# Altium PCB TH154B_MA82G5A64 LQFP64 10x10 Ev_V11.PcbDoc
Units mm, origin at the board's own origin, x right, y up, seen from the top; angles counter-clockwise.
Board outline 72.4 x 66 mm, 2 copper layers (Top Layer, Bottom Layer); 55 components, 79 nets, 354 pads, 133 vias.
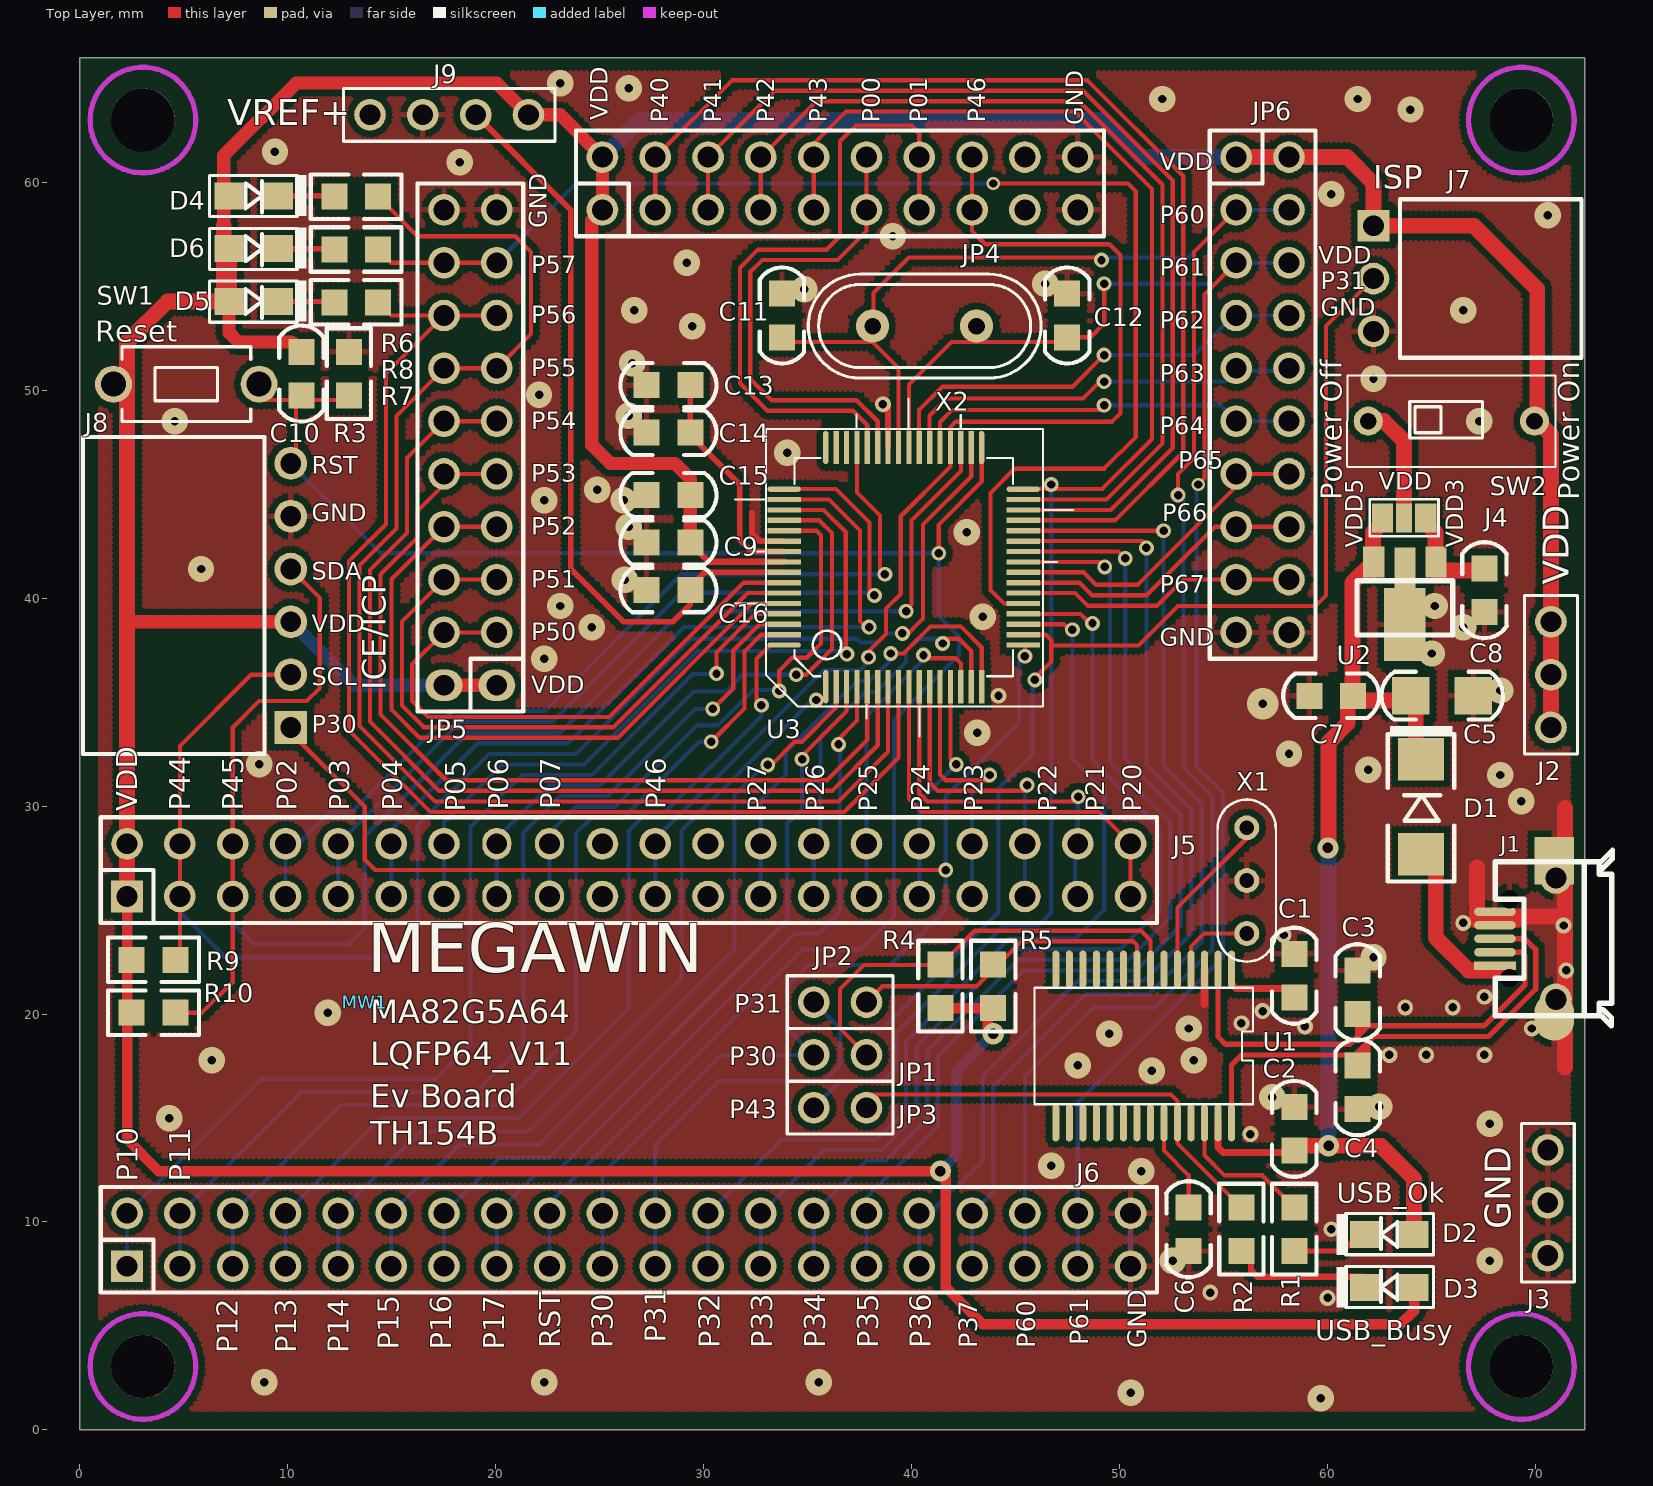
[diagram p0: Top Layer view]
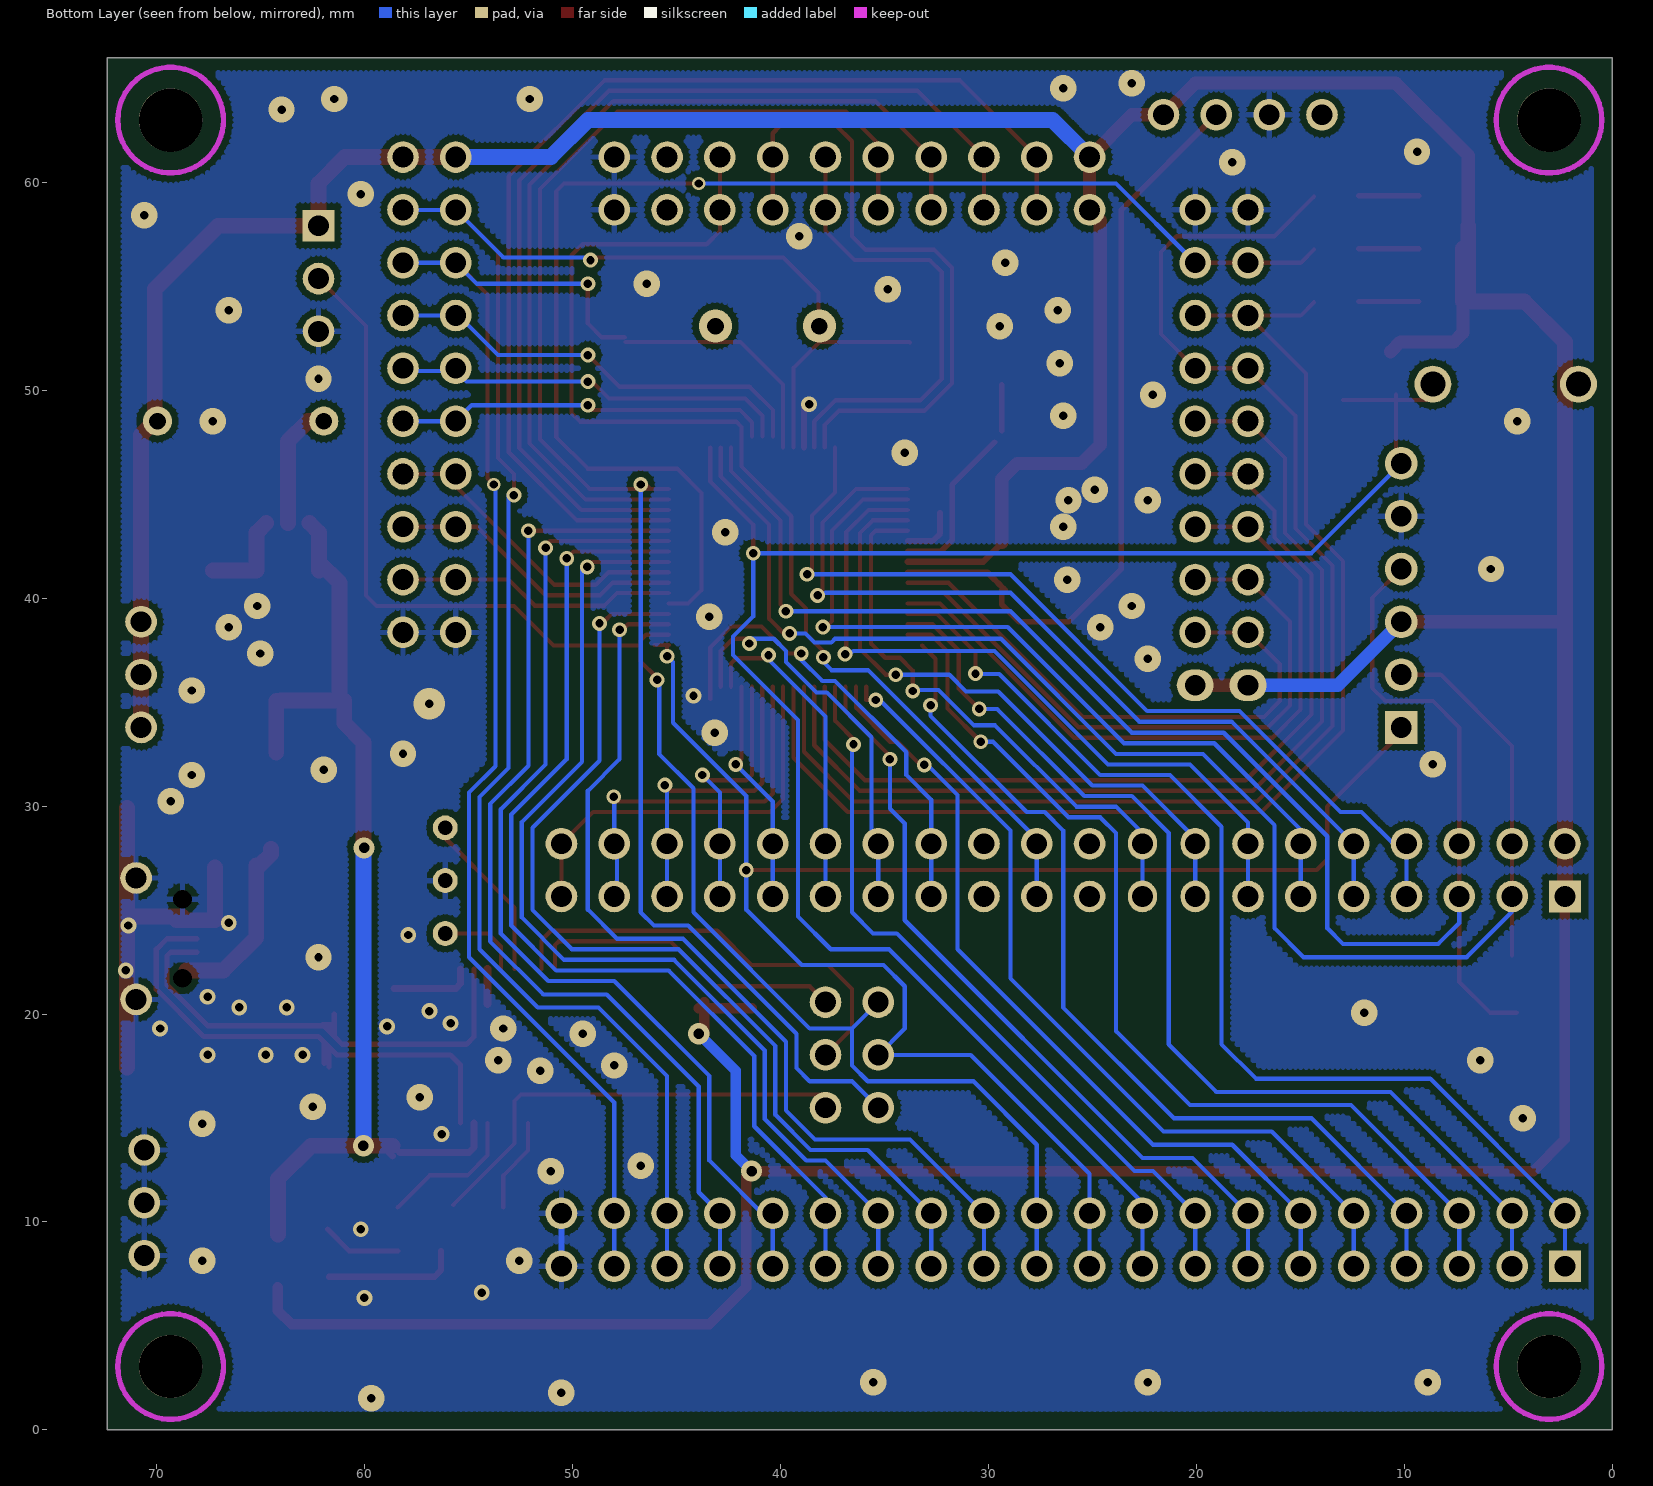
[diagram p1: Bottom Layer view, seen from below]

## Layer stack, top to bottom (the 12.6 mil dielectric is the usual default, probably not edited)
Top Layer: signal copper 0.0356
Dielectric: dielectric 0.32, FR-4, Dk 4.8
Bottom Layer: signal copper 0.0356

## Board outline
0,0 72.4,0 72.4,66 0,66

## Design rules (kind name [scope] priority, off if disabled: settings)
Clearance 12 [All] p1 off: gap=0.305
Clearance 10 [All] p2 off: gap=0.254
Clearance 6 [All] p3: gap=0.152
ComponentClearance [All] p1 off: gap=0.254 collisioncheckmode=3 verticalgap=0.254 showdistances=FALSE
HoleSize [All] p1: absolutevalues=TRUE maxlimit=12.7 minlimit=0.025 maxpercent=80.000 minpercent=20.000
MinimumSolderMaskSliver [All] p1 off: minsoldermaskwidth=0.254
PolygonConnect VIA [ISVIA] p1: connectstyle=Direct reliefconductorwidth=0.254 reliefentries=4 polygonreliefangle="90 Angle"
PolygonConnect [All] p2: connectstyle=Relief reliefconductorwidth=0.254 reliefentries=4 polygonreliefangle="90 Angle"
RoomDefinition "TH154B_MA82G5A64 LQFP64 10x10 Ev_V10" [InComponentClass('TH154B_MA82G5A64 LQFP64 10x10 Ev_V10')] p1: confinementstyle=ConfineIn formatcopy=TRUE lockcomponents=FALSE outline -6.858,-3.556 77.47,-3.556 77.47,69.85 -6.858,69.85
RoutingVias [All] p1: holewidth=0.406 width=0.635 viastyle="Through Hole" minholewidth=0.406 minwidth=0.61 maxholewidth=0.711 maxwidth=1.27
SilkToSilkClearance [All] p1 off: silktosilkclearance=0.254
SilkscreenOverComponentPads [All] p1 off: minsilkscreentomaskgap=0.254
SolderMaskExpansion [All] p1 off: expansion=0.102
Width [All] p1: maxlimit=5.08 minlimit=0.152 preferedwidth=0.254
23 further rules are at their usual default settings.

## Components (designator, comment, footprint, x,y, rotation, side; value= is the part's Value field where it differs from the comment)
C1 "4.7uF" 0805C 58.42,21.844 r90 top
C2 "0.1uF" 0805C 58.42,14.478 r270 top
C3 "15pF" 0805C 61.468,21.045 r90 top
C4 "15pF" 0805C 61.468,16.473 r270 top
C5 "4.7uF" 1206C 65.532,35.306 r0 top
C6 "0.1uF" 0805C 53.34,9.652 r90 top
C7 "0.1uF" 0805C 60.198,35.306 r180 top
C8 "4.7uF" 0805C 67.564,40.386 r270 top
C9 "0.1uF" 0805C 28.321,42.672 r0 top
C10 "1u" 0805C 10.668,50.8 r270 top
C11 "NC" 0805C 33.782,53.594 r90 top
C12 "NC" 0805C 47.498,53.594 r90 top
C13 "4.7uF" 0805C 28.321,50.245 r180 top
C14 "0.1uF" 0805C 28.321,47.959 r0 top
C15 "4.7uF" 0805C 28.321,44.958 r180 top
C16 "0.1uF" 0805C 28.321,40.386 r180 top
D1 "1N5817" D5817_SMD_1 64.516,29.972 r270 top
D2 "Yellow" 0805D 62.992,9.398 r180 top
D3 "Red" 0805D 62.992,6.858 r180 top
D4 "Green" 0805D 8.382,59.35 r0 top
D5 "Red" 0805D 8.382,54.27 r0 top
D6 "Green" 0805D 8.382,56.81 r0 top
J1 "Micro USB母座" JACK_USB_SMD290X220P065 68.072,23.622 r180 top
J2 "*" PS3P254 70.764,33.782 r90 top
J3 "*" PS3P254 70.612,13.462 r270 top
J4 "*" JUMP3_SMD 63.703,43.866 r0 top
J5 "*" PS20X2P254#1 2.286,25.654 r0 top
J6 "*" PS20X2P254#2 2.286,7.874 r0 top
J7 "*" PS3P254f_90 62.23,57.912 r270 top
J8 "*" PS6P254F_90 10.16,33.782 r90 top
J9 "CON4" PS4P254 21.59,63.246 r180 top
JP1 "JUMPER2" PS2P254 35.306,18.034 r0 top
JP2 "JUMPER2" PS2P254 35.306,20.574 r0 top
JP3 "JUMPER2" PS2P254 35.306,15.494 r0 top
JP4 "*" PS10X2P254#1 25.146,58.674 r0 top
JP5 "*" PS10X2P254#2 20.066,35.814 r90 top
JP6 "*" PS10X2P254#1 55.626,61.214 r270 top
MW1 "MW-A4" MEGAWIN_T 13.716,20.574 r0 top
R1 "1K" 0805R 58.42,9.652 r270 top
R2 "1K" 0805R 55.88,9.652 r270 top
R3 "47K" 0805R 12.954,50.8 r270 top
R4 "4.7K" 0805R 41.402,21.336 r90 top
R5 "4.7K" 0805R 43.942,21.336 r90 top
R6 "1K" 0805R 13.301,59.309 r180 top
R7 "1K" 0805R 13.301,54.229 r180 top
R8 "1K" 0805R 13.301,56.769 r180 top
R9 "4.7K" 0805R 3.556,22.606 r180 top
R10 "4.7K" 0805R 3.556,20.066 r180 top
SW1 "SW TACT-SPST" SW_T_2P 5.136,50.292 r0 top
SW2 "-" DIP2_SW 61.976,48.514 r0 top
U1 "MA101_TSSOP28" SSOP28_220P065 51.177,18.462 r180 top
U2 "AIC1734-33(SOT-89)" SOT89 63.74,41.732 r180 top
U3 "MA82G5A64 (10x10)" QFP64_10X10P050 35.886,35.744 r90 top locked (schematic designator U1)
X1 "6MHz" X3P 56.134,23.876 r90 top
X2 "NC" X49U 40.64,53.086 r180 top

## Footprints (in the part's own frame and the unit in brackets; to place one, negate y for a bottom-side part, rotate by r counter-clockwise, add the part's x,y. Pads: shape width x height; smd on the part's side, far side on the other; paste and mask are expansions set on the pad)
0805C [mm]
  rect 1.25x1.25 smd: 1(-1.05,0) 2(1.05,0)
  silkscreen extent -2.31,-1.07 2.31,1.07
0805D [mm]
  rect 1.4x1.3 smd: 1(-1.192,0) 2(1.192,0)
  silkscreen extent -2.12,-1 2.53,0.98
0805R [mm]
  rect 1.25x1.25 smd: 1(-1.05,0) 2(1.05,0)
  silkscreen extent -2.18,-1.07 2.18,1.07
1206C [mm]
  rect 1.8x1.8 smd: 1(-1.5,0) 2(1.5,0)
  silkscreen extent -2.92,-1.15 2.92,1.16
D5817_SMD_1 [mil]
  rect 80x86.61 smd: 1(90,0) 2(-90,0)
  silkscreen extent -153,-63 142,63
DIP2_SW [mm]
  round 1.4 hole 0.8: 1(0,0) 2(8,0)
  silkscreen extent -1.02,-2.2 9.02,2.2
JACK_USB_SMD290X220P065 [mm]
  rect 1.9x1.8 on Mech2: 0(-2.85,-1.15) 0(-2.85,1.15)
  round 0.8 hole 0.9 unplated: 1(-0.7,1.9) 5(-0.7,-1.9)
  rect 2x0.4 smd: 1(0,1.3)
  oval 2x0.4 smd: 2(0,0.65) 3(0,0) 4(0,-0.65) 5(0,-1.3)
  round 1.524 hole 1: 5(-2.931,2.921) 5(-2.931,-2.921)
  oval 1.9x2.3 smd: 5(-2.85,3.75)
  rect 1.9x2.3 smd: 5(-2.85,-3.75)
  silkscreen extent -5.65,-4.25 -0.01,4.2
JUMP3_SMD [mil]
  rect 40x55 smd: 1(-41,0) 3(41,0)
  rect 30x55 smd: 2(0,0)
  silkscreen extent -65,-35 65,35
MEGAWIN_T [mm]
PS2P254 [mil]
  round 60 hole 39.37: 1(0,0) 2(100,0)
  silkscreen extent -50,-50 150,50
PS3P254 [mil]
  round 60 hole 39.37: 1(0,0) 2(100,0) 3(200,0)
  silkscreen extent -50,-50 250,50
PS3P254f_90 [mil]
  rect 60x60 hole 39.37: 1(0,0)
  round 60 hole 39.37: 2(100,0) 3(200,0)
  silkscreen extent -50,50 250,394
PS4P254 [mil]
  round 60 hole 39.37: 1(0,0) 2(100,0) 3(200,0) 4(300,0)
  silkscreen extent -50,-50 350,50
PS6P254F_90 [mil]
  rect 62x62 hole 39.37: 1(0,0)
  round 62 hole 39.37: 2(100,0) 3(200,0) 4(300,0) 5(400,0) 6(500,0)
  silkscreen extent -50,50 550,394
PS10X2P254#1 [mil]
  round 60 hole 39.37: 1(0,0) 2(0,100) 3(100,0) 4(100,100) 5(200,0) 6(200,100) 7(300,0) 8(300,100) 9(400,0) 10(400,100) 11(500,0) 12(500,100) 13(600,0) 14(600,100) 15(700,0) 16(700,100) 17(800,0) 18(800,100) 19(900,0) 20(900,100)
  silkscreen extent -50,-50 950,150
PS10X2P254#2 [mil]
  oval 60x70 hole 39.37: 1(0,0) 2(0,100)
  round 60 hole 39.37: 3(100,0) 4(100,100) 5(200,0) 6(200,100) 7(300,0) 8(300,100) 9(400,0) 10(400,100) 11(500,0) 12(500,100) 13(600,0) 14(600,100) 15(700,0) 16(700,100) 17(800,0) 18(800,100) 19(900,0) 20(900,100)
  silkscreen extent -50,-50 950,150
PS20X2P254#1 [mil]
  rect 60x60 hole 39.37: 1(0,0)
  round 60 hole 39.37: 2(0,100) 3(100,0) 4(100,100) 5(200,0) 6(200,100) 7(300,0) 8(300,100) 9(400,0) 10(400,100) 11(500,0) 12(500,100) 13(600,0) 14(600,100) 19(900,0) 20(900,100) 21(1000,0) 22(1000,100) 23(1100,0) 24(1100,100) 25(1200,0) 26(1200,100) 27(1300,0) 28(1300,100) 29(1400,0) 30(1400,100) 31(1500,0) 32(1500,100) 33(1600,0) 34(1600,100) 35(1700,0) 36(1700,100) 37(1800,0) 38(1800,100) 39(1900,0) 40(1900,100)
  oval 55x60 hole 39.37: 15(700,0) 16(700,100) 17(800,0) 18(800,100)
  silkscreen extent -50,-50 1950,150
PS20X2P254#2 [mil]
  rect 60x60 hole 39.37: 1(0,0)
  round 60 hole 39.37: 2(0,100) 3(100,0) 4(100,100) 5(200,0) 6(200,100) 7(300,0) 8(300,100) 9(400,0) 10(400,100) 11(500,0) 12(500,100) 13(600,0) 14(600,100) 15(700,0) 16(700,100) 17(800,0) 18(800,100) 19(900,0) 20(900,100) 21(1000,0) 22(1000,100) 23(1100,0) 24(1100,100) 25(1200,0) 26(1200,100) 27(1300,0) 28(1300,100) 29(1400,0) 30(1400,100) 31(1500,0) 32(1500,100) 33(1600,0) 34(1600,100) 35(1700,0) 36(1700,100) 37(1800,0) 38(1800,100) 39(1900,0) 40(1900,100)
  silkscreen extent -50,-50 1950,150
QFP64_10X10P050 [mm]
  oval 1.6x0.254 smd: 1(0,0) 33(11.5,-7.5) 48(11.5,0)
  rect 1.6x0.254 smd: 2(0,-0.5) 3(0,-1) 4(0,-1.5) 5(0,-2) 6(0,-2.5) 7(0,-3) 8(0,-3.5) 9(0,-4) 10(0,-4.5) 11(0,-5) 12(0,-5.5) 13(0,-6) 14(0,-6.5) 15(0,-7) 16(0,-7.5) 34(11.5,-7) 35(11.5,-6.5) 36(11.5,-6) 37(11.5,-5.5) 38(11.5,-5) 39(11.5,-4.5) 40(11.5,-4) 41(11.5,-3.5) 42(11.5,-3) 43(11.5,-2.5) 44(11.5,-2) 45(11.5,-1.5) 46(11.5,-1) 47(11.5,-0.5)
  rect 0.254x1.6 smd: 17(2,-9.5) 18(2.5,-9.5) 19(3,-9.5) 20(3.5,-9.5) 21(4,-9.5) 22(4.5,-9.5) 23(5,-9.5) 24(5.5,-9.5) 25(6,-9.5) 26(6.5,-9.5) 27(7,-9.5) 28(7.5,-9.5) 29(8,-9.5) 30(8.5,-9.5) 31(9,-9.5) 50(9,2) 51(8.5,2) 52(8,2) 53(7.5,2) 54(7,2) 55(6.5,2) 56(6,2) 57(5.5,2) 58(5,2) 59(4.5,2) 60(4,2) 61(3.5,2) 62(3,2) 63(2.5,2)
  oval 0.254x1.6 smd: 32(9.5,-9.5) 49(9.5,2) 64(2,2)
  silkscreen extent -2.4,-11.9 13.86,4.36
SOT89 [mm]
  rect 1.016x1.5 smd: 1(-1.5,0) 3(1.5,0)
  rect 2x3.5 smd: 2(0,3)
  rect 1.016x2.6 smd: 2(0,0.6)
  silkscreen extent -2.3,0.9 2.3,3.5
SSOP28_220P065 [mm]
  oval 0.343x1.778 smd: 1(-4.225,-3.7) 2(-3.575,-3.7) 3(-2.925,-3.7) 4(-2.275,-3.7) 5(-1.625,-3.7) 6(-0.975,-3.7) 7(-0.325,-3.7) 8(0.325,-3.7) 9(0.975,-3.7) 10(1.625,-3.7) 11(2.275,-3.7) 12(2.925,-3.7) 13(3.575,-3.7) 14(4.225,-3.7) 15(4.225,3.7) 16(3.575,3.7) 17(2.925,3.7) 18(2.275,3.7) 19(1.625,3.7) 20(0.975,3.7) 21(0.325,3.7) 22(-0.325,3.7) 23(-0.975,3.7) 24(-1.625,3.7) 25(-2.275,3.7) 26(-2.925,3.7) 27(-3.575,3.7) 28(-4.225,3.7)
  silkscreen extent -5.25,-2.8 5.25,2.8
SW_T_2P [mm]
  round 1.778 hole 1.2: 1(-3.5,0) 2(3.5,0)
  silkscreen extent -3.1,-1.8 3.1,1.8
X3P [mm]
  round 1.2 hole 0.711: 1(0,0) 2(5.08,0) 3(2.54,0)
  silkscreen extent -1.36,-1.4 6.44,1.4
X49U [mm]
  round 1.6 hole 0.8: 1(-2.5,0) 2(2.5,0)
  silkscreen extent -5.6,-2.5 5.6,2.5

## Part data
C1 C5 C8 C13 C15: library part CAP
C2 C3 C4 C6 C7 C9 C14 C16: library part "CAP NP"
C10: library part C
C11 C12: library part "C NP"
D1: library part DIODE_ZD, "Schottky Diode"
D2 D3 D4 D5 D6: library part LED
J1: library part CON5, "Connector"
J2 J3 J4 J7: library part CON3
J5 J6: library part CON40A
J8: library part CON6
JP4 JP5 JP6: library part CON10X2
R1 R2 R4 R5 R6 R7 R8: library part R_Dup1
R3 R9 R10: library part R
SW2: library part SW-2
U2: library part AIC1734-33(SOT-89)_0
U3: library part MG82FG5A64_LQFP64
X1: library part CRYSTAL_RC
X2: library part CRYSTAL

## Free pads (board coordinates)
  round 3.048 hole 3.048 unplated: 0(3.048,3.048) 0(3.048,62.992) 0(69.342,3.048) 0(69.342,62.992)

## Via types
v1: diameter 1.27, hole 0.406, Top Layer to Bottom Layer, tented both sides, 65 vias
v2: diameter 0.711, hole 0.406, Top Layer to Bottom Layer, tented both sides, 41 vias
v3: diameter 0.762, hole 0.406, Top Layer to Bottom Layer, tented both sides, 20 vias
v4: diameter 1.016, hole 0.508, Top Layer to Bottom Layer, tented both sides, 4 vias
v5: diameter 0.635, hole 0.406, Top Layer to Bottom Layer, tented both sides, 2 vias
v6: diameter 1.524, hole 0.406, Top Layer to Bottom Layer, tented both sides, 1 vias

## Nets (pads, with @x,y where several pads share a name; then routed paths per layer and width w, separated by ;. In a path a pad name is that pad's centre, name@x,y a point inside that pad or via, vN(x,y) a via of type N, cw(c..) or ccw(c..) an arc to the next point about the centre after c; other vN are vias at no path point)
D+: C4.1 J1.3 U1.28 | length 24.9
  Top Layer w0.254: U1.28 55.402,17.556 55.88,18.034 61.341,18.034 62.23,18.923 67.76,18.923 70.028,21.191 70.028,23.112 69.518,23.622 J1.3 ; C4.1@61.722,17.45 61.722,18.39 ; C4.1@61.951,17.628 61.951,18.567
D-: C3.1 J1.2 U1.2 | length 24.3
  Top Layer w0.254: U1.2 54.752,18.908 55.118,18.542 61.087,18.542 61.468,18.923 ; C3.1 C3.1@61.468,19.486 ; 61.62,19.279 61.692,19.351 ; C3.1@61.722,19.431 C3.1@61.976,19.431 ; J1.2 69.353,22.972 69.52,22.805 69.52,21.401 67.55,19.431 C3.1@61.976,19.431 ; 61.468,18.923 C3.1@61.976,19.431 ; 61.468,18.923 C3.1@61.468,19.486 ; C3.1@61.468,19.486 62.031,19.486 C3.1@61.976,19.431
GND_POWER: C1.2 C2.1 C3.2 C4.2 C5.2 C6.1 C7.2 C8.2 C9.1 C11.2 C12.2 C13.2 C14.1 C15.2 C16.2 J1.4 J1.5 J3.1 J3.2 J3.3 J6.39 J6.40 J7.3 J8.5 J9.3 JP4.19 JP4.20 JP5.19 JP5.20 JP6.19 JP6.20 R3.1 U1.3 U2.2 U3.42 U3.54 X1.3 | length 28.3
  Top Layer w0.279: 32.334,44.094 32.334,43.104 32.694,42.744 U3.54 ; U3.42 v3@38.886,49.327
  Top Layer w0.381: 54.102,20.472 U1.3
  Top Layer w0.762: 67.205,24.512 69.07,24.512 ; 67.205,24.578 67.205,27.044 ; 68.797,24.69 71.263,24.69 ; 71.447,17.424 71.447,22.098 71.447,29.914
  Bottom Layer w0.279: J6.39 J6.40
  other v1: 59.69,1.524 50.546,1.778 8.89,2.286 22.352,2.286 35.56,2.286 52.578,8.128 67.818,8.128 51.054,12.446 46.736,12.7 67.818,14.732 4.318,14.986 62.509,15.545 57.353,16.002 51.562,17.272 48.006,17.526 6.35,17.78 53.594,17.78 49.53,19.05 53.34,19.304 11.938,20.066 62.23,22.733 69.342,30.226 68.326,31.496 61.976,31.75 8.636,32.004 58.166,32.512 43.18,33.528 68.326,35.56 22.352,37.084 65.024,37.338 24.638,38.608 66.548,38.608 43.434,39.116 23.114,39.624 65.172,39.624 26.214,40.894 5.842,41.402 42.672,43.18 26.416,43.434 22.352,44.704 26.162,44.704 24.892,45.212 34.036,46.99 4.572,48.514 67.31,48.514 26.416,48.768 22.098,49.784 62.23,50.546 26.581,51.306 29.464,53.086 26.67,53.848 66.548,53.848 34.849,54.864 46.441,55.118 29.21,56.134 39.116,57.404 70.612,58.42 60.198,59.436 18.288,60.96 9.398,61.468 64.008,63.5 52.07,64.008 61.468,64.008 26.416,64.516 23.114,64.77
  other v3: 60.02,6.35 54.381,6.604 60.198,9.652 56.312,14.224 62.992,18.034 64.77,18.034 67.564,18.034 69.85,19.304 58.928,19.406 55.88,19.558 56.896,20.142 63.754,20.32 66.04,20.32 67.564,20.828 71.501,22.098 57.912,23.8 71.374,24.257 66.548,24.384 44.196,35.306 38.633,49.327
  other v6: 56.902,34.928
MA101_RX: JP2.2 R5.2 U1.8 | length 15.6
  Top Layer w0.203: JP2.2 38.608,21.336 43.136,21.336 45.295,23.495 50.673,23.495 50.852,23.316 U1.8 U1.8@50.852,22.277
MA101_TX: JP1.2 R4.2 U1.7 | length 25.3
  Top Layer w0.203: JP1.2 36.576,19.304 36.576,21.209 37.719,22.352 41.402,22.352 43.053,24.003 48.768,24.003 ; 44.831,24.003 48.768,24.003 ; U1.7@51.502,22.165 U1.7 51.502,23.549 51.048,24.003 48.768,24.003
NetC1_1: C1.1 U1.1 | length 4.5
  Top Layer w0.33: U1.1@55.402,21.687 U1.1 55.402,21.458 55.626,21.234 C1.1@58.598,21.234
NetC6_2: C6.2 U1.23 | length 4.6
  Top Layer w0.203: U1.23 52.152,13.431 53.34,12.243 C6.2
NetC13_1: C13.1 C14.2 U3.55 | length 10.1
  Top Layer w0.279: C14.2@29.371,48.052 C13.1 ; C14.2@29.718,47.498 31.75,45.466 31.75,42.799 32.305,42.244 U3.55
NetD1_1: D1.1 J1.1 | length 8.5
  Top Layer w0.762: D1.1@64.516,27.94 D1.1 D1.1@65.024,27.178 ; D1.1@65.227,27.153 65.227,23.673 66.802,22.098 68.58,22.098
NetD2_2: D2.2 R1.2 | length 3.8
  Top Layer w0.254: R1.2 60.75,8.602 D2.2@61.8,9.652
NetD3_2: D3.2 R2.2 | length 6.4
  Top Layer w0.305: R2.2@56.337,8.602 56.337,7.671 56.642,7.366 D3.2@61.724,7.366
NetD4_2: D4.2 R6.2 | length 2.9
  Top Layer w0.254: D4.2@9.32,59.35 D4.2 R6.2@12.21,59.35
NetD5_2: D5.2 R7.2 | length 2.9
  Top Layer w0.254: D5.2@9.32,54.27 D5.2 R7.2@12.21,54.27
NetD6_2: D6.2 R8.2 | length 2.9
  Top Layer w0.254: D6.2@9.32,56.81 D6.2 R8.2@12.21,56.81
NetJ4_2: J4.2 SW2.1 | length 6.1
  Top Layer w0.762: SW2.1 62.738,48.514 63.703,47.549 J4.2 J4.2@63.703,43.612
NetU1_4: U1.4 X1.1 | length 4.5
  Top Layer w0.203: U1.4 53.452,23.241 54.087,23.876 X1.1 X1.1@56.642,23.876
NetU1_5: U1.5 X1.2 | length 8.4
  Top Layer w0.203: U1.5 52.802,25.116 X1.2@56.642,28.956
P00: JP4.11 JP4.12 U3.43 | length 23.3
  Top Layer w0.203: JP4.12 JP4.11 37.846,57.658 36.449,56.261 32.838,56.261 32.258,55.681 32.258,50.546 33.29,49.514 37.379,49.514 38.386,48.507 U3.43
P01: JP4.13 JP4.14 U3.44 | length 31.6
  Top Layer w0.203: U3.44 37.886,48.332 37.204,49.014 33.083,49.014 31.758,50.339 31.758,55.888 32.631,56.761 35.933,56.761 36.576,57.404 36.576,61.976 37.338,62.738 40.005,62.738 40.386,62.357 JP4.14 JP4.13
P02: J5.7 J5.8 U3.45 | length 43.3
  Top Layer w0.203: U3.45 37.386,45.08 38.498,43.967 v2@38.498,41.148
  Bottom Layer w0.203: J5.7 J5.8 10.541,28.194 12.065,29.718 13.081,29.718 17.932,34.569 22.377,34.569 28.956,41.148 v2(38.735,41.148)
P03: J5.9 J5.10 U3.49 | length 41.2
  Top Layer w0.203: U3.49 36.384,45.244 37.99,43.637 v2@37.99,40.132
  Bottom Layer w0.203: J5.9 J5.10 18.313,34.061 22.758,34.061 28.956,40.259 37.846,40.259
  other v2: 38.227,40.132
P04: J5.11 J5.12 U3.50 | length 39.3
  Top Layer w0.203: U3.50 36.045,44.744 37.533,43.256 37.533,38.895 v2@37.897,38.532
  Bottom Layer w0.203: J5.11 J5.12 14.986,28.854 19.152,33.02 23.495,33.02 29.083,38.608 37.821,38.608 v2@37.897,38.532
  other v2: 37.973,38.608
P05: J5.13 J5.14 U3.51 | length 35.8
  Top Layer w0.203: U3.51 35.783,44.244 36.847,43.18 36.847,37.397 v2@36.982,37.262
  Bottom Layer w0.203: J5.13 J5.14 17.526,29.21 20.32,32.004 24.257,32.004 29.718,37.465 36.516,37.465 v2@36.847,37.133
  other v2: 36.906,37.313
P06: J5.15 J5.16 U3.52 | length 30.8
  Top Layer w0.203: U3.52 35.572,43.744 36.187,43.129 36.187,37.559 34.95,36.322 v2(34.468,36.322)
  Bottom Layer w0.203: J5.15 J5.16 20.066,28.448 22.606,30.988 25.019,30.988 29.54,35.509 31.085,35.509 31.898,36.322 v2(34.468,36.322)
P07: J5.17 J5.18 U3.53 | length 27.5
  Top Layer w0.203: v2(33.655,35.535) 33.655,36.525 34.263,37.133 34.974,37.133 35.654,37.813 35.654,43.028 35.437,43.244 U3.53
  Bottom Layer w0.203: J5.17 J5.18 22.606,28.702 23.876,29.972 25.781,29.972 29.693,33.884 30.709,33.884 32.41,35.585 v2@33.655,35.585
P10: J6.1 J6.2 U3.61 | length 52.8
  Top Layer w0.203: v2(30.632,36.373) 30.632,37.389 32.488,39.244 U3.61
  Bottom Layer w0.203: J6.1 J6.2 8.763,16.891 17.145,16.891 18.796,18.542 18.796,29.007 21.285,31.496 24.638,31.496 29.489,36.347 v2@30.632,36.347
P11: J6.3 J6.4 U3.62 | length 51.6
  Top Layer w0.203: v2(30.455,34.671) 31.441,35.657 31.441,37.486 32.699,38.744 U3.62
  Bottom Layer w0.203: J6.3 J6.4 10.668,16.256 19.05,16.256 21.336,18.542 21.336,25.4 ; 21.336,24.13 21.336,25.4 ; v2(30.455,34.671) 29.591,34.671 25.4,30.48 23.114,30.48 21.336,28.702 21.336,25.4
P12: J6.5 J6.6 U3.63 | length 48
  Top Layer w0.203: v2(30.378,33.096) 31.979,34.696 31.979,37.44 32.783,38.244 U3.63
  Bottom Layer w0.203: J6.5 J6.6 12.573,15.621 20.32,15.621 23.876,19.177 23.876,23.622 ; 23.876,23.368 23.876,23.622 ; v2(30.378,33.096) 29.794,33.096 26.162,29.464 24.638,29.464 23.876,28.702 23.876,23.622
P13: J6.7 J6.8 U3.64 | length 44.6
  Top Layer w0.203: v2@32.563,34.849 32.563,37.084 U3.64@33.198,37.719
  Bottom Layer w0.203: J6.7 J6.8 14.478,14.986 21.082,14.986 26.416,20.32 26.416,24.003 ; 26.416,23.368 26.416,24.003 ; v2(32.791,34.849) 32.791,34.341 28.169,29.718 27.305,29.718 26.416,28.829 26.416,24.003
P14: J6.9 J6.10 U3.1 | length 41.6
  Top Layer w0.203: v2@35.501,35.103 35.886,35.103 U3.1 U3.1@35.886,35.306
  Bottom Layer w0.203: J6.9 J6.10 16.383,14.351 21.59,14.351 28.956,21.717 28.956,24.384 ; 28.956,24.13 28.956,24.384 ; v2@35.331,35.204 28.956,28.829 28.956,24.384
  other v2: 35.433,35.103
P15: J6.11 J6.12 U3.2 | length 39.4
  Top Layer w0.203: v2(33.096,31.979) 33.096,32.055 33.35,32.055 34.392,33.096 34.747,33.096 36.386,34.735 U3.2
  Bottom Layer w0.203: J6.11 J6.12 18.288,13.716 22.098,13.716 31.496,23.114 31.496,30.531 v2@33.02,32.055
P16: J6.13 J6.14 U3.3 | length 37.3
  Top Layer w0.203: v2@34.671,32.334 36.886,34.549 U3.3
  Bottom Layer w0.203: J6.13 J6.14 20.193,13.081 22.606,13.081 34.036,24.511 34.036,29.159 34.747,29.87 v2(34.747,32.258)
P17: J6.15 J6.16 U3.4 | length 36.2
  Top Layer w0.203: v2@36.373,33.096 37.386,34.109 U3.4
  Bottom Layer w0.203: J6.15 J6.16 22.098,12.446 22.987,12.446 34.417,23.876 35.56,23.876 36.576,24.892 v2@36.576,32.969
  other v2: 36.5,32.969
P20: J5.39 J5.40 U3.9 | length 19.5
  Top Layer w0.203: U3.9 39.886,30.345 40.513,29.718 49.022,29.718 J5.40 J5.39
P21: J5.37 J5.38 U3.10 | length 17.9
  Top Layer w0.203: U3.10 40.386,30.607 40.767,30.226 v2@48.031,30.226
  Bottom Layer w0.203: J5.38@47.879,28.194 47.879,25.781 J5.37 ; J5.38 v2@48.006,30.582
  other v2: 48.031,30.455
P22: J5.35 J5.36 U3.11 | length 14.9
  Top Layer w0.203: U3.11 40.886,31.123 41.275,30.734 v2@45.568,30.734
  Bottom Layer w0.203: J5.35 J5.36 45.466,30.912 v2(45.568,31.013)
P23: J5.33 J5.34 U3.12 | length 12.9
  Top Layer w0.203: U3.12 41.386,31.512 41.656,31.242 v2@43.764,31.242
  Bottom Layer w0.203: J5.33 J5.34 42.926,30.658 v2(43.764,31.496)
P24: J5.31 J5.32 U3.13 | length 10.9
  Top Layer w0.203: U3.13 41.886,32.282 v2(42.164,32.004)
  Bottom Layer w0.203: J5.31 J5.32 40.386,30.226 v2(42.164,32.004)
P25: J5.29 J5.30 U3.14 | length 15.6
  Top Layer w0.203: v2(40.589,37.262) 40.742,37.109 42.139,37.109 42.386,36.862 U3.14
  Bottom Layer w0.203: J5.29 J5.30 37.846,34.315 v2@40.589,37.059
P26: J5.27 J5.28 U3.15 | length 19
  Top Layer w0.203: v2@41.504,38.049 42.291,38.049 42.886,37.454 U3.15
  Bottom Layer w0.203: J5.27 J5.28 ; J5.28@35.636,28.524 35.636,29.718 ; 35.636,29.566 35.636,29.718 ; v2@41.504,38.049 40.335,38.049 39.751,37.465 39.751,36.932 38.278,35.458 37.783,35.458 35.636,33.312 35.636,29.718
  other v2: 41.504,37.821
P27: J5.25 J5.26 U3.16 | length 22.4
  Top Layer w0.203: v2(39.014,37.338) 39.624,37.338 40.919,38.633 42.393,38.633 43.386,37.64 U3.16 U3.16@43.386,35.15
  Bottom Layer w0.203: J5.25 J5.26 32.766,30.302 33.96,31.496 33.96,32.588 37.389,36.017 37.998,36.017 39.014,37.033 v2(39.014,37.338)
P30/RXD: J6.19 J6.20 J8.1 JP1.1 U3.17 | length 80.7
  Top Layer w0.203: J8.1@10.16,33.528 13.716,29.972 13.716,27.432 14.224,26.924 v2(41.656,26.924) ; U3.17 U3.17@45.466,37.744 ; v2(45.466,37.211) U3.17@45.466,37.744 ; U3.17@46.076,37.744 U3.17@45.466,37.744
  Bottom Layer w0.203: J6.19 J6.20 25.146,12.319 30.861,18.034 JP1.1 34.036,19.304 34.036,21.336 35.052,22.352 38.989,22.352 41.656,25.019 v2(41.656,26.924) 41.656,30.48 45.187,34.011 45.187,36.932 v2(45.466,37.211)
P31/TXD: J6.21 J6.22 J7.2 JP2.1 U3.18 | length 75.6
  Top Layer w0.203: U3.18 46.465,38.244 46.736,37.973 46.736,37.719 ; v2@45.974,36.195 46.736,36.957 46.736,37.719 ; J7.2 59.944,53.086 59.944,40.132 59.436,39.624 52.832,39.624 50.927,37.719 46.736,37.719
  Bottom Layer w0.203: J6.21 J6.22 27.686,13.716 30.734,16.764 35.814,16.764 36.576,17.526 36.576,19.304 ; JP2.1 36.576,19.304 ; v2@45.847,36.068 45.847,32.512 44.196,30.861 44.196,24.892 38.608,19.304 36.576,19.304
  other v2: 45.949,36.068
P32: J6.23 J6.24 U3.19 | length 46.1
  Top Layer w0.203: U3.19 47.337,38.744 v2@47.676,38.405
  Bottom Layer w0.203: J6.23 J6.24 33.782,13.97 38.354,13.97 39.751,15.367 39.751,18.669 44.704,23.622 47.879,23.622 49.276,25.019 49.276,30.734 47.752,32.258 v2(47.752,38.481)
P33: J6.25 J6.26 U3.20 | length 48
  Top Layer w0.203: U3.20 48.132,39.244 v2@48.463,38.913
  Bottom Layer w0.203: J6.25 J6.26 35.814,13.462 38.564,13.462 40.259,15.157 40.259,18.459 44.914,23.114 50.045,23.114 51.943,25.012 51.943,28.956 48.717,32.182 v2(48.717,38.786)
P34: J6.27 J6.28 U3.25 | length 49.8
  Top Layer w0.203: U3.25 49.061,41.744 v2(49.305,41.5)
  Bottom Layer w0.203: J6.27 J6.28 37.846,12.954 38.775,12.954 40.767,14.946 40.767,18.248 45.125,22.606 50.419,22.606 52.451,24.638 52.451,29.235 49.559,32.128 49.559,41.5 v2(49.305,41.5)
P35: J6.29 J6.30 U3.26 | length 49.6
  Top Layer w0.203: U3.26 49.958,42.244 v2(50.292,41.91)
  Bottom Layer w0.203: J6.29 J6.30 37.846,11.176 41.275,14.605 41.275,17.983 45.39,22.098 50.8,22.098 52.959,24.257 52.959,29.591 50.292,32.258 v2(50.292,41.91)
P36: J6.31 J6.32 U3.27 | length 48.4
  Top Layer w0.203: U3.27 51.109,42.744
  Bottom Layer w0.203: J6.31 40.386,9.906 43.434,12.954 43.434,17.018 48.006,21.59 51.181,21.59 53.467,23.876 53.467,29.845 51.308,32.004 v2(51.308,42.418)
P37: J6.33 J6.34 U3.28 | length 49.2
  Top Layer w0.203: U3.28 v2(52.133,43.244)
  Bottom Layer w0.203: J6.33 J6.34 43.942,11.43 43.942,16.51 48.368,20.936 51.416,20.936 53.975,23.495 53.975,30.099 52.133,31.941 v2(52.133,43.244)
P40: JP4.3 JP4.4 U3.29 | length 53.7
  Top Layer w0.203: JP4.3 JP4.4 31.376,64.904 48.47,64.904 53.078,60.295 53.078,47.02 49.802,43.744 U3.29
P41: JP4.5 JP4.6 U3.30 | length 49.3
  Top Layer w0.203: JP4.5 JP4.6 33.416,64.404 48.262,64.404 52.578,60.088 52.578,47.227 49.595,44.244 U3.30
P42: JP4.7 JP4.8 U3.31 | length 44.9
  Top Layer w0.203: JP4.7 JP4.8 35.456,63.904 48.055,63.904 52.078,59.881 52.078,47.434 49.388,44.744 U3.31
P43: JP3.1 JP4.9 JP4.10 U3.32 | length 78
  Top Layer w0.203: JP4.9 JP4.10 35.306,61.849 36.861,63.404 47.848,63.404 51.578,59.674 51.578,47.641 49.181,45.244 46.26,45.244 ; U3.32 46.26,45.244 ; v2@46.609,45.593 46.26,45.244
  Bottom Layer w0.203: JP3.1 36.576,16.764 38.608,16.764 39.243,17.399 39.243,19.05 44.45,24.257 46.101,24.257 46.736,24.892 v2@46.736,45.244
  other v2: 46.736,45.466
P44: J5.3 J5.4 J8.2 R9.1 U3.34 | length 73.5
  Top Layer w0.203: R9.1@4.826,22.826 J5.3 J5.4 4.826,32.893 8.255,36.322 J8.2 ; v2@39.713,38.163 40.564,39.014 40.564,43.536 42.886,45.858 U3.34
  Bottom Layer w0.203: J5.3 4.826,24.917 7.01,22.733 14.859,22.733 16.256,24.13 16.256,29.083 19.685,32.512 23.876,32.512 29.413,38.049 37.389,38.049 37.567,37.871 38.379,37.871 38.811,38.303 v2(39.573,38.303) ; J5.4 J5.4@4.826,28.575
P45: J5.5 J5.6 J8.4 R10.1 U3.35 | length 80.3
  Top Layer w0.203: R10.1 5.893,20.066 7.366,21.539 J5.5 J5.6 7.366,33.782 8.636,35.052 10.922,35.052 11.557,35.687 11.557,40.005 J8.4 ; v2@39.675,39.37 40.005,39.7 40.005,43.739 42.386,46.12 U3.35
  Bottom Layer w0.203: J5.5@7.366,25.146 J5.5 7.366,24.384 8.382,23.368 12.954,23.368 13.716,24.13 13.716,28.55 18.694,33.528 23.114,33.528 28.956,39.37 v2(39.751,39.37) ; J5.6 J5.6@7.366,28.829
P46: J5.21 J5.22 JP4.15 JP4.16 U3.36 | length 56.6
  Top Layer w0.203: v2(37.948,37.16) 37.948,37.44 38.786,38.278 38.786,39.497 39.497,40.208 39.497,43.942 41.886,46.331 U3.36 41.886,48.236 42.139,48.489 49.657,48.489 50.062,48.894 50.062,56.491 49.53,57.023 43.561,57.023 42.926,57.658 JP4.15 JP4.16
  Bottom Layer w0.203: J5.21 J5.22 27.686,28.423 35.801,36.538 37.554,36.538 v2@38.062,37.046
P50: JP5.3 JP5.4 U3.58 | length 27.3
  Top Layer w0.203: JP5.3 JP5.4 16.002,36.83 16.002,35.052 16.764,34.29 25.475,34.29 31.929,40.744 U3.58
P51: JP5.5 JP5.6 U3.59 | length 30.9
  Top Layer w0.203: JP5.5 JP5.6 15.502,38.87 15.502,34.845 16.557,33.79 25.682,33.79 32.136,40.244 U3.59
P52: JP5.7 JP5.8 U3.60 | length 34.5
  Top Layer w0.203: JP5.7 JP5.8 15.002,40.91 15.002,34.638 16.35,33.29 25.89,33.29 32.344,39.744 U3.60
P53: JP5.9 JP5.10 U3.5 | length 43.5
  Top Layer w0.203: JP5.9 JP5.10 17.526,45.466 16.256,44.196 16.256,42.926 14.478,41.148 14.478,34.4 17.636,31.242 35.941,31.242 37.886,33.187 U3.5
P54: JP5.11 JP5.12 U3.6 | length 48
  Top Layer w0.203: JP5.11 JP5.12 15.748,46.736 15.748,43.136 13.97,41.358 13.97,34.062 17.298,30.734 36.195,30.734 38.386,32.925 U3.6
P55: JP5.13 JP5.14 R6.1 U3.7 | length 67.8
  Top Layer w0.203: R6.1 16.256,57.404 20.955,57.404 21.717,56.642 21.717,52.705 JP5.13 ; JP5.13@20.701,51.054 JP5.13 ; U3.7 38.886,32.612 36.5,30.226 17.088,30.226 13.462,33.852 13.462,41.569 15.24,43.347 15.24,48.768 JP5.14 JP5.13
P56: JP5.15 JP5.16 R7.1 U3.8 | length 60.4
  Top Layer w0.203: R7.1 14.986,53.594 JP5.16 ; JP5.15 JP5.16 ; U3.8 39.386,32.325 36.779,29.718 16.878,29.718 12.954,33.642 12.954,41.779 14.732,43.557 14.732,50.8 JP5.16
P57: JP5.17 JP5.18 R8.1 U3.21 | length 69.4
  Top Layer w0.203: R8.1 14.986,56.134 JP5.18 JP5.17 ; 43.815,44.958 43.815,40.386 ; v5(43.942,59.944) 50.419,59.944 50.8,59.563 50.8,47.752 49.276,46.228 44.979,46.228 43.815,45.064 43.815,40.386 ; U3.21 44.457,39.744 43.815,40.386
  Bottom Layer w0.203: JP5.17 23.876,59.944 v5(43.942,59.944)
P60: C11.1 J6.35 J6.36 JP6.3 JP6.4 U3.41 X2.2 | length 93.7
  Top Layer w0.203: C11.1@33.782,52.29 33.816,52.324 X2.2@38.14,52.324 ; X2.2@38.14,52.832 X2.2@38.14,52.324 ; X2.2@38.18,52.832 38.18,54.69 39.878,56.388 49.022,56.388 v2(49.149,56.261) ; 39.386,49.04 U3.41 39.386,51.078 X2.2@38.14,52.324 ; v2(52.832,44.958) 52.832,45.974 53.594,46.736 53.594,56.642 JP6.3
  Bottom Layer w0.203: J6.35 J6.36 45.466,17.018 48.768,20.32 51.689,20.32 54.483,23.114 54.483,30.437 53.086,31.834 v2@53.086,44.958 ; v2@49.276,56.388 53.34,56.388 JP6.3 JP6.4
P61: C12.1 J6.37 J6.38 JP6.5 JP6.6 U3.40 X2.1 | length 78.5
  Top Layer w0.203: 39.886,48.556 U3.40 39.886,50.275 41.935,52.324 C12.1@47.464,52.324 ; C12.1 48.607,52.544 49.276,53.213 v2(49.276,55.118) ; v5(53.797,45.466) 54.102,45.771 54.102,54.61 JP6.5
  Bottom Layer w0.203: J6.37 J6.38 48.006,15.748 54.991,22.733 54.991,30.648 53.721,31.918 v5@53.721,45.466 ; v2(49.276,55.118) 54.61,55.118 JP6.5 JP6.6
P62: JP6.7 JP6.8 U3.39 | length 20.9
  Top Layer w0.203: U3.39@40.377,47.777 40.377,49.047 41.494,50.165 47.752,50.165 v2(49.276,51.689)
  Bottom Layer w0.203: v2(49.276,51.689) 53.594,51.689 55.499,53.594 JP6.7 JP6.8
P63: JP6.9 JP6.10 U3.38 | length 19.1
  Top Layer w0.203: U3.38@40.877,47.777 40.877,48.776 41.707,49.606 48.26,49.606 49.073,50.419 v2(49.276,50.419)
  Bottom Layer w0.203: v2(49.276,50.419) 55.118,50.419 55.626,50.927 JP6.10@58.039,50.927
P64: JP6.11 JP6.12 U3.37 | length 18.1
  Top Layer w0.203: U3.37@41.377,47.777 41.377,48.463 41.961,49.047 49.047,49.047 v2(49.276,49.276)
  Bottom Layer w0.203: v2(49.276,49.276) 54.864,49.276 JP6.11 JP6.12
P65: JP6.13 JP6.14 U3.24 | length 15.4
  Top Layer w0.203: U3.24 48.291,41.244 48.895,40.64 50.876,40.64 55.753,45.517 55.753,45.847 55.88,45.974 JP6.14
P66: JP6.15 JP6.16 U3.23 | length 14.4
  Top Layer w0.203: U3.23 48.084,40.744 48.688,40.14 51.316,40.14 54.61,43.434 JP6.15 JP6.16
P67: JP6.17 JP6.18 U3.22 | length 13.8
  Top Layer w0.203: U3.22 47.877,40.244 48.481,39.64 51.832,39.64 53.086,40.894 JP6.17 ; JP6.17@55.88,40.894 JP6.17 ; JP6.18 JP6.17
RST: C10.2 J6.17 J6.18 J8.6 R3.2 SW1.2 U3.33 | length 90.9
  Top Layer w0.203: SW1.2@8.58,50.038 SW1.2@9.088,49.53 ; SW1.2@8.636,49.53 SW1.2@9.088,49.53 ; J8.6@10.414,46.482 C10.2@10.414,49.53 ; C10.2@10.414,49.784 C10.2@10.414,49.53 ; R3.2@12.954,49.53 C10.2@10.414,49.53 ; v2@41.326,41.935 v2(41.326,42.164) 41.326,43.536 43.386,45.596 U3.33 ; SW1.2@9.088,49.53 C10.2@10.414,49.53
  Bottom Layer w0.203: J8.6 14.478,42.164 v2@41.097,42.164 ; J6.17 22.606,10.287 J6.18@22.669,10.351 ; J6.18@22.606,11.049 22.733,11.049 34.798,23.114 37.592,23.114 39.167,24.689 39.167,34.138 42.291,37.262 42.291,38.151 41.326,39.116 v2@41.326,41.935
USB_BUSY: JP3.2 R2.1 U1.24 | length 21.4
  Top Layer w0.203: JP3.2@37.719,16.129 52.492,16.129 52.802,15.819 U1.24 52.802,13.771 R2.1@55.753,10.82
USB_OK: R1.1 U1.26 | length 6.9
  Top Layer w0.203: U1.26 54.102,13.208 55.067,12.243 56.879,12.243 R1.1
VDD: C9.2 C10.1 C15.1 D3.1 D4.1 D5.1 D6.1 J2.1 J2.2 J2.3 J5.1 J5.2 J7.1 J8.3 J9.1 JP4.1 JP4.2 JP5.1 JP5.2 JP6.1 JP6.2 R4.1 R5.1 R9.2 R10.2 SW1.1 SW2.2 U3.56 | length 279.7
  Top Layer w0.305: C9.2 29.371,42.638 30.265,41.744 U3.56
  Top Layer w0.508: J5.1 2.286,13.97 3.81,12.446 v4(41.402,12.446) 41.656,12.192 41.656,6.858 43.434,5.08 63.525,5.08 64.184,5.738 D3.1 ; R4.1 R5.1@43.688,20.286 ; v4@43.688,19.05 R5.1@43.688,20.286 ; R5.1@43.688,20.574 R5.1@43.688,20.286 ; R5.1 R5.1@43.688,20.286
  Top Layer w0.635: 2.286,38.862 J8.3 ; 6.936,57.912 6.936,61.292 10.414,64.77 20.066,64.77 J9.1 23.114,63.246 JP4.2 JP4.1 24.638,58.166 24.638,47.371 25.527,46.482 28.626,46.482 29.371,45.737 C15.1 C9.2 ; D5.1 7.19,52.754 7.62,52.324 10.194,52.324 C10.1 ; JP5.2 JP5.1
  Top Layer w0.762: J5.1 J5.2@2.286,27.815 ; J5.2 2.286,38.862 2.286,52.324 4.232,54.27 6.936,54.27 D6.1@6.936,56.81 ; 6.936,57.912 D6.1@6.936,56.81 ; D5.1 D6.1 D6.1@6.936,56.81 ; JP6.1 JP6.2 60.96,61.214 62.23,59.944 J7.1 67.056,57.912 70.104,54.864 70.104,48.514 70.764,47.854 J2.3 J2.2 J2.1
  Bottom Layer w0.508: v4(41.402,12.446) 42.164,13.208 42.164,17.272 v4(43.942,19.05)
  Bottom Layer w0.635: J8.3 13.208,35.814 JP5.2
  Bottom Layer w0.762: JP4.2 26.924,62.992 49.276,62.992 51.054,61.214 JP6.1
VDD3: C8.1 J4.3 U2.1 | length 4.6
  Top Layer w0.762: J4.3@64.745,43.612 65.205,43.152 65.205,41.326 C8.1@67.319,41.326
VDD5: C2.2 C5.1 C7.1 D1.2 D2.1 J4.1 U1.27 U2.3 | length 50.9
  Top Layer w0.33: U1.27 54.752,13.574 54.991,13.335 C2.2@58.327,13.335 ; C2.2@58.674,13.174 C2.2@58.928,13.428
  Top Layer w0.762: C2.2@58.674,13.665 v4(60.071,13.665) 62.586,13.665 64.184,12.067 D2.1 ; v4@60.071,27.99 60.071,33.071 60.994,33.994 60.994,35.086 C7.1@61.214,35.086 ; U2.3@62.205,41.326 U2.3@62.205,41.732 ; J4.1@62.662,43.612 62.205,43.155 U2.3@62.205,41.732 ; C5.1@64.032,35.086 C7.1@61.214,35.086 ; D1.2@64.262,32.57 C5.1@64.262,35.052 ; C7.1@61.214,35.086 61.214,40.742 U2.3@62.205,41.732
  Bottom Layer w0.762: v4(60.071,13.665) v4@60.071,27.981
  other v4: 60.036,27.99
VREF+: C16.1 J9.2 U3.57 | length 37
  Top Layer w0.279: J9.2 23.622,58.674 23.622,41.402 26.162,38.862 28.543,38.862 29.371,39.69 C16.1 ; C16.1@29.21,40.386 C16.1@29.291,40.467 ; C16.1@29.56,40.736 C16.1@29.291,40.467 ; U3.57 30.068,41.244 C16.1@29.291,40.467
pads on no net: J1.0 J5.19 J5.20 J5.23 J5.24 J9.4 JP4.17 JP4.18 U1.6 U1.9 U1.10 U1.11 U1.12 U1.13 U1.14 U1.15 U1.16 U1.17 U1.18 U1.19 U1.20 U1.21 U1.22 U1.25 U3.46 U3.47 U3.48

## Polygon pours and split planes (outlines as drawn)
GND_POWER on Top Layer "Bottom Layer-No Net" (hatched 90Degree grid 0.254 track 0.254, remove dead copper, pour order 1001): 1.016,0.991 71.628,0.991 71.628,65.278 1.016,65.278
GND_POWER on Bottom Layer "Bottom Layer-No Net" (hatched 90Degree grid 0.254 track 0.254, remove dead copper, pour order 1001): 1.016,0.991 71.628,0.991 71.628,65.278 1.016,65.278

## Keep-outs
Keep-Out Layer:
  circle w0.254: c69.342,3.048 r2.54
  circle w0.254: c3.048,3.048 r2.54
  circle w0.254: c3.048,62.992 r2.54
  circle w0.254: c69.342,62.992 r2.54

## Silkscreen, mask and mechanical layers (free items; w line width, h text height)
Top Overlay:
  text "VDD" at 25.4,62.992 h0.84 r90
  text "P40" at 28.321,62.865 h0.84 r90
  text "P41" at 30.861,62.865 h0.84 r90
  text "P42" at 33.401,62.865 h0.84 r90
  text "P43" at 35.941,62.865 h0.84 r90
  text "P00" at 38.481,62.865 h0.84 r90
  text "P01" at 40.767,62.865 h0.84 r90
  text "P46" at 43.561,62.865 h0.84 r90
  text "VREF+" at 7.112,62.738 h1.27
  text "GND" at 48.26,62.738 h0.84 r90
  text "VDD" at 51.943,60.579 h0.84
  text "ISP" at 62.23,59.69 h1.14
  text "P60" at 51.943,58.039 h0.84
  text "GND" at 22.479,57.785 h0.84 r90
  text "VDD" at 59.563,56.083 h0.84
  text "P57" at 21.717,55.626 h0.84
  text "P61" at 51.943,55.499 h0.84
  text "P31" at 59.69,54.864 h0.84
  text "GND" at 59.69,53.594 h0.84
  text "P56" at 21.717,53.213 h0.84
  text "P62" at 51.943,52.959 h0.84
  text "Reset" at 0.762,52.324 h1.02
  text "P55" at 21.717,50.673 h0.84
  text "P63" at 51.943,50.419 h0.84
  text "P54" at 21.717,48.133 h0.84
  text "P64" at 51.943,47.879 h0.84
  text "P65" at 52.832,46.228 h0.84
  text "RST" at 11.176,45.974 h0.84
  text "P53" at 21.717,45.593 h0.84
  text "VDD" at 62.484,45.212 h0.84
  text "Power Off" at 60.706,44.704 h1.02 r90
  text "Power On" at 72.136,44.704 h1.02 r90
  text "GND" at 11.176,43.688 h0.84
  text "P66" at 52.07,43.688 h0.84
  text "P52" at 21.717,43.053 h0.84
  text "VDD5" at 61.722,42.418 h0.84 r90
  text "VDD3" at 66.548,42.418 h0.84 r90
  text "SDA" at 11.176,40.894 h0.84
  text "VDD" at 71.628,40.64 h1.27 r90
  text "P51" at 21.717,40.513 h0.84
  text "P67" at 51.943,40.259 h0.84
  text "VDD" at 11.176,38.354 h0.84
  text "P50" at 21.717,37.973 h0.84
  text "GND" at 51.943,37.719 h0.84
  text "SCL" at 11.176,35.814 h0.84
  text "ICE/ICP" at 14.732,35.56 h1.14 r90
  text "VDD" at 21.717,35.433 h0.84
  text "P30" at 11.176,33.528 h0.84
  text "P07" at 23.114,29.845 h0.97 r90
  text "P46" at 28.194,29.845 h0.97 r90
  text "P06" at 20.625,29.82 h0.97 r90
  text "P44" at 5.334,29.769 h1.02 r90
  text "P45" at 7.874,29.769 h1.02 r90
  text "P02" at 10.439,29.769 h0.97 r90
  text "P03" at 12.979,29.769 h0.97 r90
  text "P04" at 15.519,29.769 h0.97 r90
  text "VDD" at 2.769,29.743 h1.02 r90
  text "P05" at 18.542,29.718 h0.97 r90
  text "P27" at 33.02,29.718 h0.89 r90
  text "P26" at 35.814,29.718 h0.89 r90
  text "P25" at 38.354,29.718 h0.89 r90
  text "P24" at 40.894,29.718 h0.89 r90
  text "P23" at 43.434,29.718 h0.89 r90
  text "P22" at 46.99,29.718 h0.89 r90
  text "P21" at 49.276,29.718 h0.89 r90
  text "P20" at 51.054,29.718 h0.89 r90
  text "P31" at 31.496,20.066 h0.89
  text "MA82G5A64" at 13.97,19.558 h1.14
  text "LQFP64_V11" at 13.97,17.526 h1.14
  text "P30" at 31.242,17.526 h0.89
  text "Ev Board" at 13.97,15.502 h1.14
  text "P43" at 31.242,14.986 h0.89
  text "TH154B" at 13.97,13.716 h1.14
  text "P10" at 2.794,11.938 h1.02 r90
  text "P11" at 5.334,11.938 h1.02 r90
  text "USB_Ok" at 60.452,10.922 h0.97
  text "GND" at 68.834,9.652 h1.27 r90
  text "USB_Busy" at 59.436,4.318 h0.97
  text "P31" at 28.194,4.191 h1.02 r90
  text "P61" at 48.514,4.064 h0.9 r90
  text "RST" at 23.114,3.937 h1.02 r90
  text "P30" at 25.654,3.937 h1.02 r90
  text "P32" at 30.785,3.937 h1.02 r90
  text "P33" at 33.325,3.937 h1.02 r90
  text "P34" at 35.865,3.937 h1.02 r90
  text "P35" at 38.405,3.937 h1.02 r90
  text "P36" at 40.945,3.937 h1.02 r90
  text "P37" at 43.18,3.937 h0.89 r90
  text "P60" at 45.974,3.937 h0.89 r90
  text "GND" at 51.308,3.937 h0.9 r90
  text "P15" at 15.34,3.86 h1.02 r90
  text "P16" at 17.88,3.86 h1.02 r90
  text "P17" at 20.42,3.86 h1.02 r90
  text "P12" at 7.62,3.683 h1.02 r90
  text "P13" at 10.414,3.683 h1.02 r90
  text "P14" at 12.954,3.683 h1.02 r90
Mechanical 1:
  the board outline again, w0.33

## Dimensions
0,66 to 0,0 on Top Overlay
0,0 to 72.4,0 on Top Overlay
